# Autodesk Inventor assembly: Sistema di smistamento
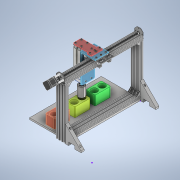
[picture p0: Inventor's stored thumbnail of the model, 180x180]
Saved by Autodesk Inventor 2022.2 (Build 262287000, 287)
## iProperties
Created: 2024-10
Part Number: Sistema di smistamento
Document SubType Name: Assembly
Designer: 18907419
Sending System: Autodesk Inventor 2025
Preprocessor: ST-DEVELOPER v20
Title: Sistema di smistamento.stp
Author: R5800u
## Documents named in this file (42)
- C:\Users\18907419\Desktop\automazione\smistamento\Sistema di smistamento.iam
- C:\Users\18907419\Desktop\automazione\smistamento\vslot-4020-verticaleipt.ipt
- C:\Users\18907419\Desktop\automazione\smistamento\Solido42.ipt
- C:\Users\18907419\Desktop\automazione\smistamento\Solido45.ipt
- C:\Users\18907419\Desktop\automazione\smistamento\Solido39.ipt
- C:\Users\18907419\Desktop\automazione\smistamento\Solido44.ipt
- C:\Users\18907419\Desktop\automazione\smistamento\Solido60.ipt
- C:\Users\18907419\Desktop\automazione\smistamento\Solido61.ipt
- C:\Users\18907419\Desktop\automazione\smistamento\Solido66.ipt
- C:\Users\18907419\Desktop\automazione\smistamento\Solido65.ipt
- C:\Users\18907419\Desktop\automazione\smistamento\Solido62.ipt
- C:\Users\18907419\Desktop\automazione\smistamento\Solido63.ipt
- C:\Users\18907419\Desktop\automazione\smistamento\Solido46.ipt
- C:\Users\18907419\Desktop\automazione\smistamento\Solido43.ipt
- C:\Users\18907419\Desktop\automazione\smistamento\Solido35.ipt
- C:\Users\18907419\Desktop\automazione\smistamento\Solido34.ipt
- C:\Users\18907419\Desktop\automazione\smistamento\Solido38.ipt
- C:\Users\18907419\Desktop\automazione\smistamento\Solido36.ipt
- C:\Users\18907419\Desktop\automazione\smistamento\Solido37.ipt
- C:\Users\18907419\Desktop\automazione\smistamento\Solido64.ipt
- C:\Users\18907419\Desktop\automazione\smistamento\Solido41.ipt
- C:\Users\18907419\Desktop\automazione\smistamento\Solido40.ipt
- C:\Users\18907419\Desktop\automazione\smistamento\Piatto guida.iam
- C:\Users\18907419\Desktop\automazione\smistamento\angolare_cilindro.ipt
- C:\Users\18907419\Desktop\automazione\smistamento\2600400100CP_100-A--.iam
- C:\Users\18907419\Desktop\automazione\smistamento\piastra_posteriore_cilindro.ipt
- C:\Users\18907419\Desktop\automazione\smistamento\Assieme_ventosa.iam
- C:\Users\18907419\Desktop\automazione\smistamento\vslot-4020-verticale-2.ipt
- C:\Users\18907419\Desktop\automazione\smistamento\piano_lavoro_1.ipt
- C:\Users\18907419\Desktop\automazione\smistamento\pezzo.ipt
- C:\Users\18907419\Desktop\automazione\smistamento\scatole_pezzi.ipt
- C:\Users\18907419\Desktop\automazione\smistamento\vslot-4020-orizzontale.ipt
- C:\Users\18907419\Desktop\automazione\smistamento\Cast Corner Bracket.ipt
- C:\Users\18907419\Desktop\automazione\smistamento\Cast Corner Bracket_MIR.ipt
- C:\Users\18907419\Desktop\automazione\smistamento\Cast Corner Bracket_MIR1.ipt
- C:\Users\18907419\Desktop\automazione\smistamento\Cast Corner Bracket_MIR_MIR.ipt
- C:\Users\18907419\Desktop\automazione\smistamento\AS 1420 - 1973 - M5 x 20.ipt
- C:\Users\18907419\Desktop\automazione\smistamento\AS 1420 - 1973 - M6 x 16.ipt
- C:\Users\18907419\Desktop\automazione\smistamento\AS 1420 - 1973 - M3 x 12.ipt
- C:\Users\18907419\Desktop\automazione\smistamento\BARRA FILETTATA T8.ipt
- C:\Users\18907419\Desktop\automazione\smistamento\sostegno laterale.ipt
- C:\Users\18907419\Desktop\automazione\smistamento\sostegno laterale_MIR.ipt
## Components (64 placed, 41 different names)
1. vslot-4020-verticaleipt:1
2. Solido42:1
3. Solido45:1
4. Solido39:1
5. Solido44:1
6. Solido60:1
7. Solido61:1
8. Solido66:1
9. Solido65:1
10. Solido62:1
11. Solido63:1
12. Solido46:1
13. Solido43:1
14. Solido35:1
15. Solido34:1
16. Solido38:1
17. Solido36:1
18. Solido37:1
19. Solido64:1
20. Solido41:1
21. Solido40:1
22. Piatto guida:1 [sub-assembly]
23. angolare_cilindro:1
24. 2600400100CP_100-A--:1 [sub-assembly]
25. piastra_posteriore_cilindro:1
26. Assieme_ventosa:1 [sub-assembly]
27. vslot-4020-verticale-2:1
28. vslot-4020-verticale-2:2
29. piano_lavoro_1:1
30. pezzo:1
31. scatole_pezzi:1
32. scatole_pezzi:2
33. scatole_pezzi:3
34. vslot-4020-orizzontale:1
35. Cast Corner Bracket:3
36. Cast Corner Bracket:4
37. Cast Corner Bracket:11
38. Cast Corner Bracket_MIR:1
39. Cast Corner Bracket_MIR:2
40. Cast Corner Bracket_MIR:3
41. Cast Corner Bracket_MIR1:1
42. Cast Corner Bracket_MIR1:2
43. Cast Corner Bracket_MIR1:3
44. Cast Corner Bracket_MIR_MIR:1
45. Cast Corner Bracket_MIR_MIR:2
46. Cast Corner Bracket_MIR_MIR:3
47. AS 1420 - Metrico M5 x 20:1
48. AS 1420 - Metrico M5 x 20:2
49. AS 1420 - Metrico M5 x 20:3
50. AS 1420 - Metrico M5 x 20:4
51. AS 1420 - Metrico M5 x 20:5
52. AS 1420 - Metrico M5 x 20:6
53. AS 1420 - Metrico M5 x 20:7
54. AS 1420 - Metrico M5 x 20:8
55. AS 1420 - Metrico M5 x 20:9
56. AS 1420 - Metrico M5 x 20:10
57. AS 1420 - Metrico M5 x 20:11
58. AS 1420 - Metrico M5 x 20:12
59. AS 1420 - Metrico M6 x 16:1
60. AS 1420 - Metrico M6 x 16:2
61. AS 1420 - Metrico M3 x 12:1
62. BARRA FILETTATA T8:1
63. sostegno laterale:2
64. sostegno laterale_MIR:1
